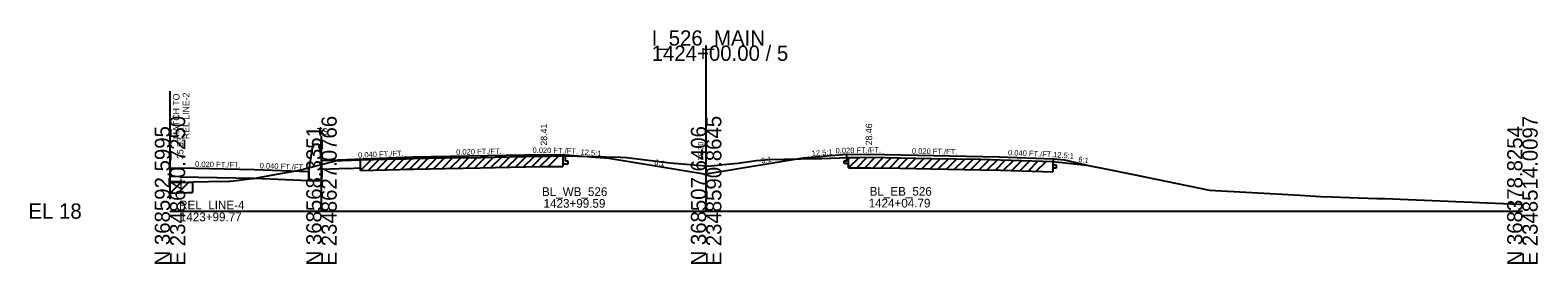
# Model space of a CAD drawing. Extents: x -170 to 2527928, y -10 to 1619750.
# Drawn here: x 3974.3 to 4251.4, y 3490.3 to 3533.2 of the extents above; entities that cross this region are included whole.
import ezdxf

# ---------------------------------------------------------------- set-up
doc = ezdxf.new("R2010")
doc.units = 0
for name, color, linetype in [('RD_GPK_XS_Cell', 7, 'Continuous'), ('RD_PD_NOISE-WALL-GM', 7, 'Continuous'), ('RD_XS_Base', 7, 'Continuous'), ('RD_XS_EarthShd', 7, 'Continuous'), ('RD_XS_ExGround', 7, 'Continuous'), ('RD_XS_ExPaveRet', 7, 'Continuous'), ('RD_XS_MatchLine', 7, 'Continuous'), ('RD_XS_Pave', 7, 'Continuous'), ('RD_XS_PaveShd', 7, 'Continuous'), ('RD_XS_TieSlope', 7, 'Continuous'), ('RD_XS_TX_Elev_EX', 7, 'Continuous'), ('RD_XS_TX_Slope', 7, 'Continuous'), ('RD_XS_TX_Station', 7, 'Continuous')]:
    doc.layers.add(name, color=color, linetype=linetype)

msp = doc.modelspace()

# ---------------------------------------------------------------- linework, layer by layer
at = {"layer": 'RD_GPK_XS_Cell'}
for p, q in [((4098.52, 3500), (4098.52, 3530.39)), ((4000, 3500), (4027.84, 3500)), ((4027.84, 3500), (4098.52, 3500)), ((4098.52, 3500), (4248.52, 3500))]:
    msp.add_line(p, q, dxfattribs=at)
at = {"layer": 'RD_PD_NOISE-WALL-GM'}
for p, q in [((4025.51, 3507.26), (4026.31, 3512.27)), ((4026.31, 3512.27), (4027.36, 3512.27)), ((4027.36, 3512.27), (4027.84, 3509.27)), ((4027.84, 3510), (4027.84, 3505.63)), ((4025.51, 3507.26), (4025.51, 3505.63)), ((4025.51, 3505.63), (4027.84, 3505.63))]:
    msp.add_line(p, q, dxfattribs=at)
at = {"layer": 'RD_XS_Base'}
for p, q in [((4072.65, 3509.19), (4072.65, 3510.33)), ((4124.38, 3509.24), (4124.38, 3510.38)), ((4027.84, 3507.94), (4027.84, 3509.08)), ((4032.65, 3507.82), (4027.84, 3507.63)), ((4032.65, 3507.82), (4034.99, 3507.92)), ((4072.22, 3508.7), (4072.65, 3508.69)), ((4073.15, 3509.18), (4072.65, 3509.19)), ((4072.65, 3508.69), (4073.15, 3508.68)), ((4073.15, 3508.68), (4073.15, 3509.18)), ((4123.88, 3509.23), (4124.38, 3509.24)), ((4123.88, 3508.73), (4123.88, 3509.23)), ((4124.38, 3508.74), (4123.88, 3508.73)), ((4124.38, 3508.74), (4124.69, 3508.75)), ((4162.26, 3507.96), (4162.88, 3507.93)), ((4162.38, 3508.45), (4162.38, 3509.59)), ((4162.88, 3508.43), (4162.38, 3508.45)), ((4162.88, 3507.93), (4162.88, 3508.43)), ((4001.81, 3506.3), (4000.01, 3506.33)), ((4001.81, 3506.3), (4015.51, 3506.03)), ((4015.51, 3506.03), (4025.51, 3505.63)), ((4025.51, 3505.63), (4025.51, 3507.26))]:
    msp.add_line(p, q, dxfattribs=at)
at = {"layer": 'RD_XS_EarthShd'}
for p, q in [((4072.65, 3510.33), (4080.65, 3509.69)), ((4124.38, 3510.38), (4116.38, 3509.74))]:
    msp.add_line(p, q, dxfattribs=at)
at = {"layer": 'RD_XS_ExGround'}
msp.add_lwpolyline([(4000, 3505.22), (4003.19, 3505.3), (4004.13, 3505.32), (4004.4, 3505.34), (4007.08, 3505.4), (4010.84, 3505.49), (4011.13, 3505.5), (4012.69, 3505.68), (4014.97, 3505.97), (4015.46, 3506), (4016.33, 3506.17), (4019.61, 3506.75), (4023.78, 3507.49), (4027.84, 3508.57), (4029.75, 3509.07), (4030.41, 3509.25), (4030.76, 3509.26), (4031.61, 3509.29), (4034.99, 3509.39), (4042.23, 3509.57), (4043.36, 3509.6), (4043.49, 3509.61), (4044.75, 3509.64), (4050.63, 3509.75), (4057.05, 3509.86), (4062.48, 3509.96), (4068.24, 3510.08), (4070.07, 3510.11), (4072.22, 3510.13), (4082.77, 3509.89), (4083.9, 3509.85), (4091.94, 3508.86), (4092.55, 3508.79), (4093.39, 3508.73), (4098.52, 3508.3), (4098.83, 3508.27), (4102.35, 3508.64), (4104.32, 3508.82), (4107.77, 3509.27), (4109.99, 3509.5), (4118.89, 3509.67), (4119.44, 3509.67), (4119.73, 3509.68), (4124.69, 3509.83), (4126.78, 3509.86), (4128.73, 3509.89), (4134.18, 3509.79), (4139.87, 3509.68), (4149.02, 3509.51), (4152.59, 3509.43), (4160.33, 3509.19), (4162.26, 3509.12), (4167.84, 3508.5), (4168.41, 3508.43), (4169.08, 3508.32), (4171.88, 3507.75), (4177.08, 3506.74), (4181.21, 3505.84), (4191.05, 3503.85), (4207.66, 3502.93), (4211.41, 3502.67), (4213.49, 3502.62), (4216.75, 3502.49), (4221.75, 3502.31), (4223.26, 3502.28), (4247.91, 3501.28), (4248.52, 3501.23)], dxfattribs=at)
at = {"layer": 'RD_XS_ExPaveRet'}
for p, q in [((4034.99, 3507.47), (4036.96, 3509.44)), ((4034.99, 3507.47), (4034.99, 3509.39)), ((4034.99, 3507.47), (4042.23, 3507.65)), ((4036.49, 3507.51), (4038.46, 3509.48)), ((4037.99, 3507.55), (4039.96, 3509.51)), ((4039.49, 3507.59), (4041.46, 3509.55)), ((4040.99, 3507.62), (4042.96, 3509.59)), ((4042.23, 3507.65), (4043.36, 3507.68)), ((4042.49, 3507.66), (4044.46, 3509.63)), ((4043.36, 3507.68), (4043.49, 3507.69)), ((4043.49, 3507.69), (4044.75, 3507.72)), ((4043.99, 3507.7), (4045.95, 3509.66)), ((4044.75, 3507.72), (4050.63, 3507.83)), ((4045.49, 3507.74), (4047.45, 3509.69)), ((4046.99, 3507.77), (4048.95, 3509.72)), ((4048.49, 3507.79), (4050.45, 3509.75)), ((4049.99, 3507.82), (4051.94, 3509.77)), ((4050.63, 3507.83), (4057.05, 3507.94)), ((4051.49, 3507.85), (4053.44, 3509.8)), ((4052.99, 3507.87), (4054.94, 3509.82)), ((4054.49, 3507.9), (4056.44, 3509.85)), ((4055.99, 3507.92), (4057.95, 3509.87)), ((4057.05, 3507.94), (4062.48, 3508.05)), ((4057.49, 3507.95), (4059.45, 3509.9)), ((4058.99, 3507.98), (4060.95, 3509.93)), ((4060.49, 3508.01), (4062.45, 3509.96)), ((4061.99, 3508.04), (4063.95, 3509.99)), ((4062.48, 3508.05), (4068.24, 3508.16)), ((4063.49, 3508.07), (4065.45, 3510.02)), ((4064.99, 3508.1), (4066.95, 3510.05)), ((4066.49, 3508.13), (4068.45, 3510.08)), ((4067.99, 3508.16), (4069.94, 3510.1)), ((4068.24, 3508.16), (4070.07, 3508.19)), ((4069.49, 3508.18), (4071.43, 3510.12)), ((4070.07, 3508.19), (4072.22, 3508.21)), ((4072.22, 3510.13), (4072.22, 3508.21)), ((4124.69, 3507.92), (4126.63, 3509.86)), ((4124.69, 3507.92), (4124.69, 3509.83)), ((4124.69, 3507.92), (4126.78, 3507.94)), ((4126.19, 3507.93), (4128.13, 3509.88)), ((4126.78, 3507.94), (4128.73, 3507.97)), ((4127.69, 3507.95), (4129.61, 3509.87)), ((4128.73, 3507.97), (4134.18, 3507.87)), ((4129.19, 3507.96), (4131.07, 3509.84)), ((4130.69, 3507.93), (4132.57, 3509.81)), ((4132.19, 3507.9), (4134.07, 3509.79)), ((4133.69, 3507.88), (4135.57, 3509.76)), ((4134.18, 3507.87), (4139.87, 3507.76)), ((4135.19, 3507.85), (4137.07, 3509.73)), ((4136.69, 3507.82), (4138.57, 3509.7)), ((4138.19, 3507.79), (4140.07, 3509.67)), ((4139.69, 3507.77), (4141.57, 3509.65)), ((4139.87, 3507.76), (4149.02, 3507.59)), ((4141.19, 3507.74), (4143.07, 3509.62)), ((4142.69, 3507.71), (4144.57, 3509.59)), ((4144.19, 3507.68), (4146.07, 3509.56)), ((4145.69, 3507.65), (4147.57, 3509.53)), ((4147.19, 3507.62), (4149.07, 3509.51)), ((4148.69, 3507.6), (4150.57, 3509.48)), ((4149.02, 3507.59), (4152.59, 3507.52)), ((4150.19, 3507.57), (4152.07, 3509.44)), ((4151.69, 3507.54), (4153.56, 3509.4)), ((4152.59, 3507.52), (4160.33, 3507.27)), ((4153.19, 3507.5), (4155.05, 3509.36)), ((4154.69, 3507.45), (4156.55, 3509.31)), ((4156.19, 3507.4), (4158.05, 3509.26)), ((4157.69, 3507.35), (4159.55, 3509.21)), ((4159.19, 3507.31), (4161.05, 3509.16)), ((4162.26, 3509.12), (4162.26, 3507.21)), ((4000.01, 3503.3), (4001.98, 3505.27)), ((4000.01, 3503.3), (4000.01, 3505.22)), ((4001.51, 3503.34), (4003.48, 3505.3)), ((4004.13, 3505.32), (4004.13, 3503.41)), ((4160.33, 3507.27), (4162.26, 3507.21)), ((4000.01, 3503.3), (4003.19, 3503.38)), ((4003.19, 3503.38), (4004.13, 3503.41))]:
    msp.add_line(p, q, dxfattribs=at)
at = {"layer": 'RD_XS_MatchLine'}
for p, q in [((4000.01, 3502.17), (4000.01, 3522.03)), ((4027.84, 3500), (4027.84, 3513.78))]:
    msp.add_line(p, q, dxfattribs=at)
at = {"layer": 'RD_XS_Pave'}
for p, q in [((4044.65, 3509.94), (4068.65, 3510.41)), ((4128.38, 3510.46), (4152.38, 3509.99)), ((4001.81, 3507.93), (4015.51, 3507.66))]:
    msp.add_line(p, q, dxfattribs=at)
at = {"layer": 'RD_XS_PaveShd'}
for p, q in [((4068.65, 3510.41), (4072.65, 3510.33)), ((4124.38, 3510.38), (4128.38, 3510.46)), ((4000.01, 3507.9), (4000, 3505.22)), ((4000.01, 3507.9), (4001.81, 3507.93)), ((4015.51, 3507.66), (4025.51, 3507.26)), ((4027.84, 3509.27), (4044.65, 3509.94)), ((4152.38, 3509.99), (4162.38, 3509.59))]:
    msp.add_line(p, q, dxfattribs=at)
at = {"layer": 'RD_XS_TieSlope'}
for p, q in [((4080.65, 3509.69), (4098.52, 3506.76)), ((4116.38, 3509.74), (4098.52, 3506.76)), ((4162.38, 3509.59), (4164.38, 3509.43)), ((4164.38, 3509.43), (4169.08, 3508.32))]:
    msp.add_line(p, q, dxfattribs=at)

# ---------------------------------------------------------------- texts
at = {"layer": 'RD_GPK_XS_Cell'}
for s, p in [('I_526_MAIN', (4088.52, 3530.39)), ('1424+00.00 / 5', (4088.52, 3527.59)), ('EL 18', (3974, 3498.6))]:
    msp.add_text(s, height=2.8, dxfattribs=at).set_placement(p)
for s, p in [('E 2348640.7250', (4002.8, 3490)), ('E 2348627.0766', (4030.64, 3490)), ('E 2348590.8645', (4101.32, 3490)), ('E 2348514.0097', (4251.32, 3490)), ('N 368592.5995', (4000, 3490)), ('N 368568.3351', (4027.84, 3490)), ('N 368507.6406', (4098.52, 3490)), ('N 368378.8254', (4248.52, 3490))]:
    msp.add_text(s, height=2.8, rotation=90, dxfattribs=at).set_placement(p)
at = {"layer": 'RD_XS_MatchLine'}
msp.add_text('TS', height=1.2, dxfattribs=at).set_placement((4026.98, 3514.03))
at = {"layer": 'RD_XS_TX_Elev_EX'}
msp.add_text('26.30', height=1, rotation=90, dxfattribs=at).set_placement((4098.02, 3509.3))
at = {"layer": 'RD_XS_TX_Slope'}
for s, rotation, p in [('0.040 FT./FT.', 2.2682, (4034.59, 3509.79)), ('0.020 FT./FT.', 1.1234, (4052.6, 3510.34)), ('0.020 FT./FT.', 358.8321, (4066.61, 3510.7)), ('12.5:1', 355.4261, (4075.41, 3510.37)), ('12.5:1', 4.5739, (4117.96, 3510.07)), ('0.020 FT./FT.', 1.1669, (4122.32, 3510.59)), ('0.020 FT./FT.', 358.8756, (4136.33, 3510.55)), ('0.040 FT./FT.', 357.7094, (4153.98, 3510.25)), ('12.5:1', 355.4261, (4162.24, 3509.91)), ('0.020 FT./FT.', 358.8542, (4004.61, 3508.13)), ('0.040 FT./FT.', 357.7094, (4016.47, 3507.87)), ('6:1', 350.5377, (4088.94, 3508.52)), ('6:1', 9.4623, (4108.71, 3508.74)), ('6:1', 352.6182, (4166.87, 3509.03))]:
    msp.add_text(s, height=1, rotation=rotation, dxfattribs=at).set_placement(p)
at = {"layer": 'RD_XS_TX_Station'}
for s, p in [('MATCH TO', (4001.75, 3513.21)), ('REL LINE-2', (4003.55, 3513.21)), (' 28.41', (4069.31, 3511.58)), (' 28.46', (4129.03, 3511.63)), (' 25.93', (4002.47, 3509.11))]:
    msp.add_text(s, height=1.2, rotation=90, dxfattribs=at).set_placement(p)
for s, p in [('REL_LINE-4', (4001.68, 3500.31)), ('BL_WB_526', (4068.36, 3502.76)), ('1423+99.59', (4068.65, 3500.61)), ('1424+04.79', (4128.38, 3500.66)), ('BL_EB_526', (4128.57, 3502.82)), ('1423+99.77', (4001.81, 3498.13))]:
    msp.add_text(s, height=1.6, dxfattribs=at).set_placement(p)

doc.saveas('drawing.dxf')
